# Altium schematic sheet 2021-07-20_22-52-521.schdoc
size 222 x 111 mm; SheetNumber: 1; SheetTotal: 1
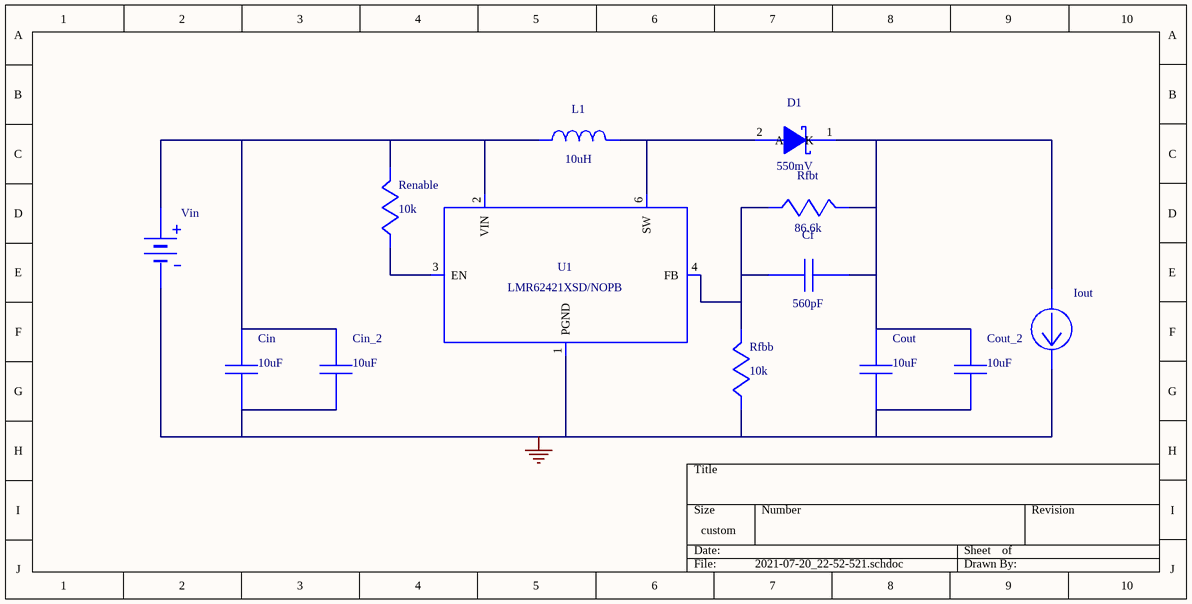
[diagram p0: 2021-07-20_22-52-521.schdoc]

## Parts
Cf  value 560pF  (hidden comment: GRM1555C1H561JA01J)
Cin  value 10uF  (hidden comment: C0805C106K8PACTU)
Cin_2  value 10uF  (hidden comment: C0805C106K8PACTU)
Cout  value 10uF  (hidden comment: GRM31CR61C106KA88L)
Cout_2  value 10uF  (hidden comment: GRM31CR61C106KA88L)
D1  value 550mV  (hidden comment: SS24FL)
Iout  WB_CURRENT_LOAD  (value not drawn)
L1  value 10uH  (hidden comment: SRN6045-100M)
Renable  value 10k  (hidden comment: RC0201FR-0710KL)
Rfbb  value 10k  (hidden comment: RC0201FR-0710KL)
Rfbt  value 86.6k  (hidden comment: RC0201FR-0786K6L)
U1  LMR62421XSD/NOPB
Vin  WB_BATTERY  (value not drawn)

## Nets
0: Cin.2 Cin_2.2 Cout.2 Cout_2.2 Iout.2(-) Rfbb.2 U1.1(PGND) U1.5(AGND) U1.7(DAP) Vin.2(-)
NetCf_1: Cf.1 Cout.1 Cout_2.1 D1.1(K) Iout.1(+) Rfbt.1
NetCf_2: Cf.2 Rfbb.1 Rfbt.2 U1.4(FB)
NetCin_1: Cin.1 Cin_2.1 L1.1 Renable.1 U1.2(VIN) Vin.1(+)
NetD1_2: D1.2(A) L1.2 U1.6(SW)
NetRenable_2: Renable.2 U1.3(EN)

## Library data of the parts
Cf = GRM1555C1H561JA01J: GRM1555C1H561JA0; Manufacturer Name: MuRata
Cin Cin_2 = C0805C106K8PACTU: Manufacturer Name: Kemet
Cout Cout_2 = GRM31CR61C106KA88L: GRM31CR61C106KA8; Manufacturer Name: MuRata
D1 = SS24FL: Manufacturer Name: Fairchild Semiconductor
L1 = SRN6045-100M: Manufacturer Name: Bourns
Renable Rfbb = RC0201FR-0710KL: Manufacturer Name: Yageo
Rfbt = RC0201FR-0786K6L: Manufacturer Name: Yageo
U1 = LMR62421XSD/NOPB: Manufacturer Name: Texas Instruments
